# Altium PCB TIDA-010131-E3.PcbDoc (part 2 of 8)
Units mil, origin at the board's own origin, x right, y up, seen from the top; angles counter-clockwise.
Board outline 6889.76 x 5118.11 mil, 6 copper layers (Top Layer, GND Layer, Signal Layer 1, Signal Layer 2, PWR Layer, Bottom Layer), stack 58.5 mil thick; 758 components, 455 nets, 2194 pads, 1156 vias.
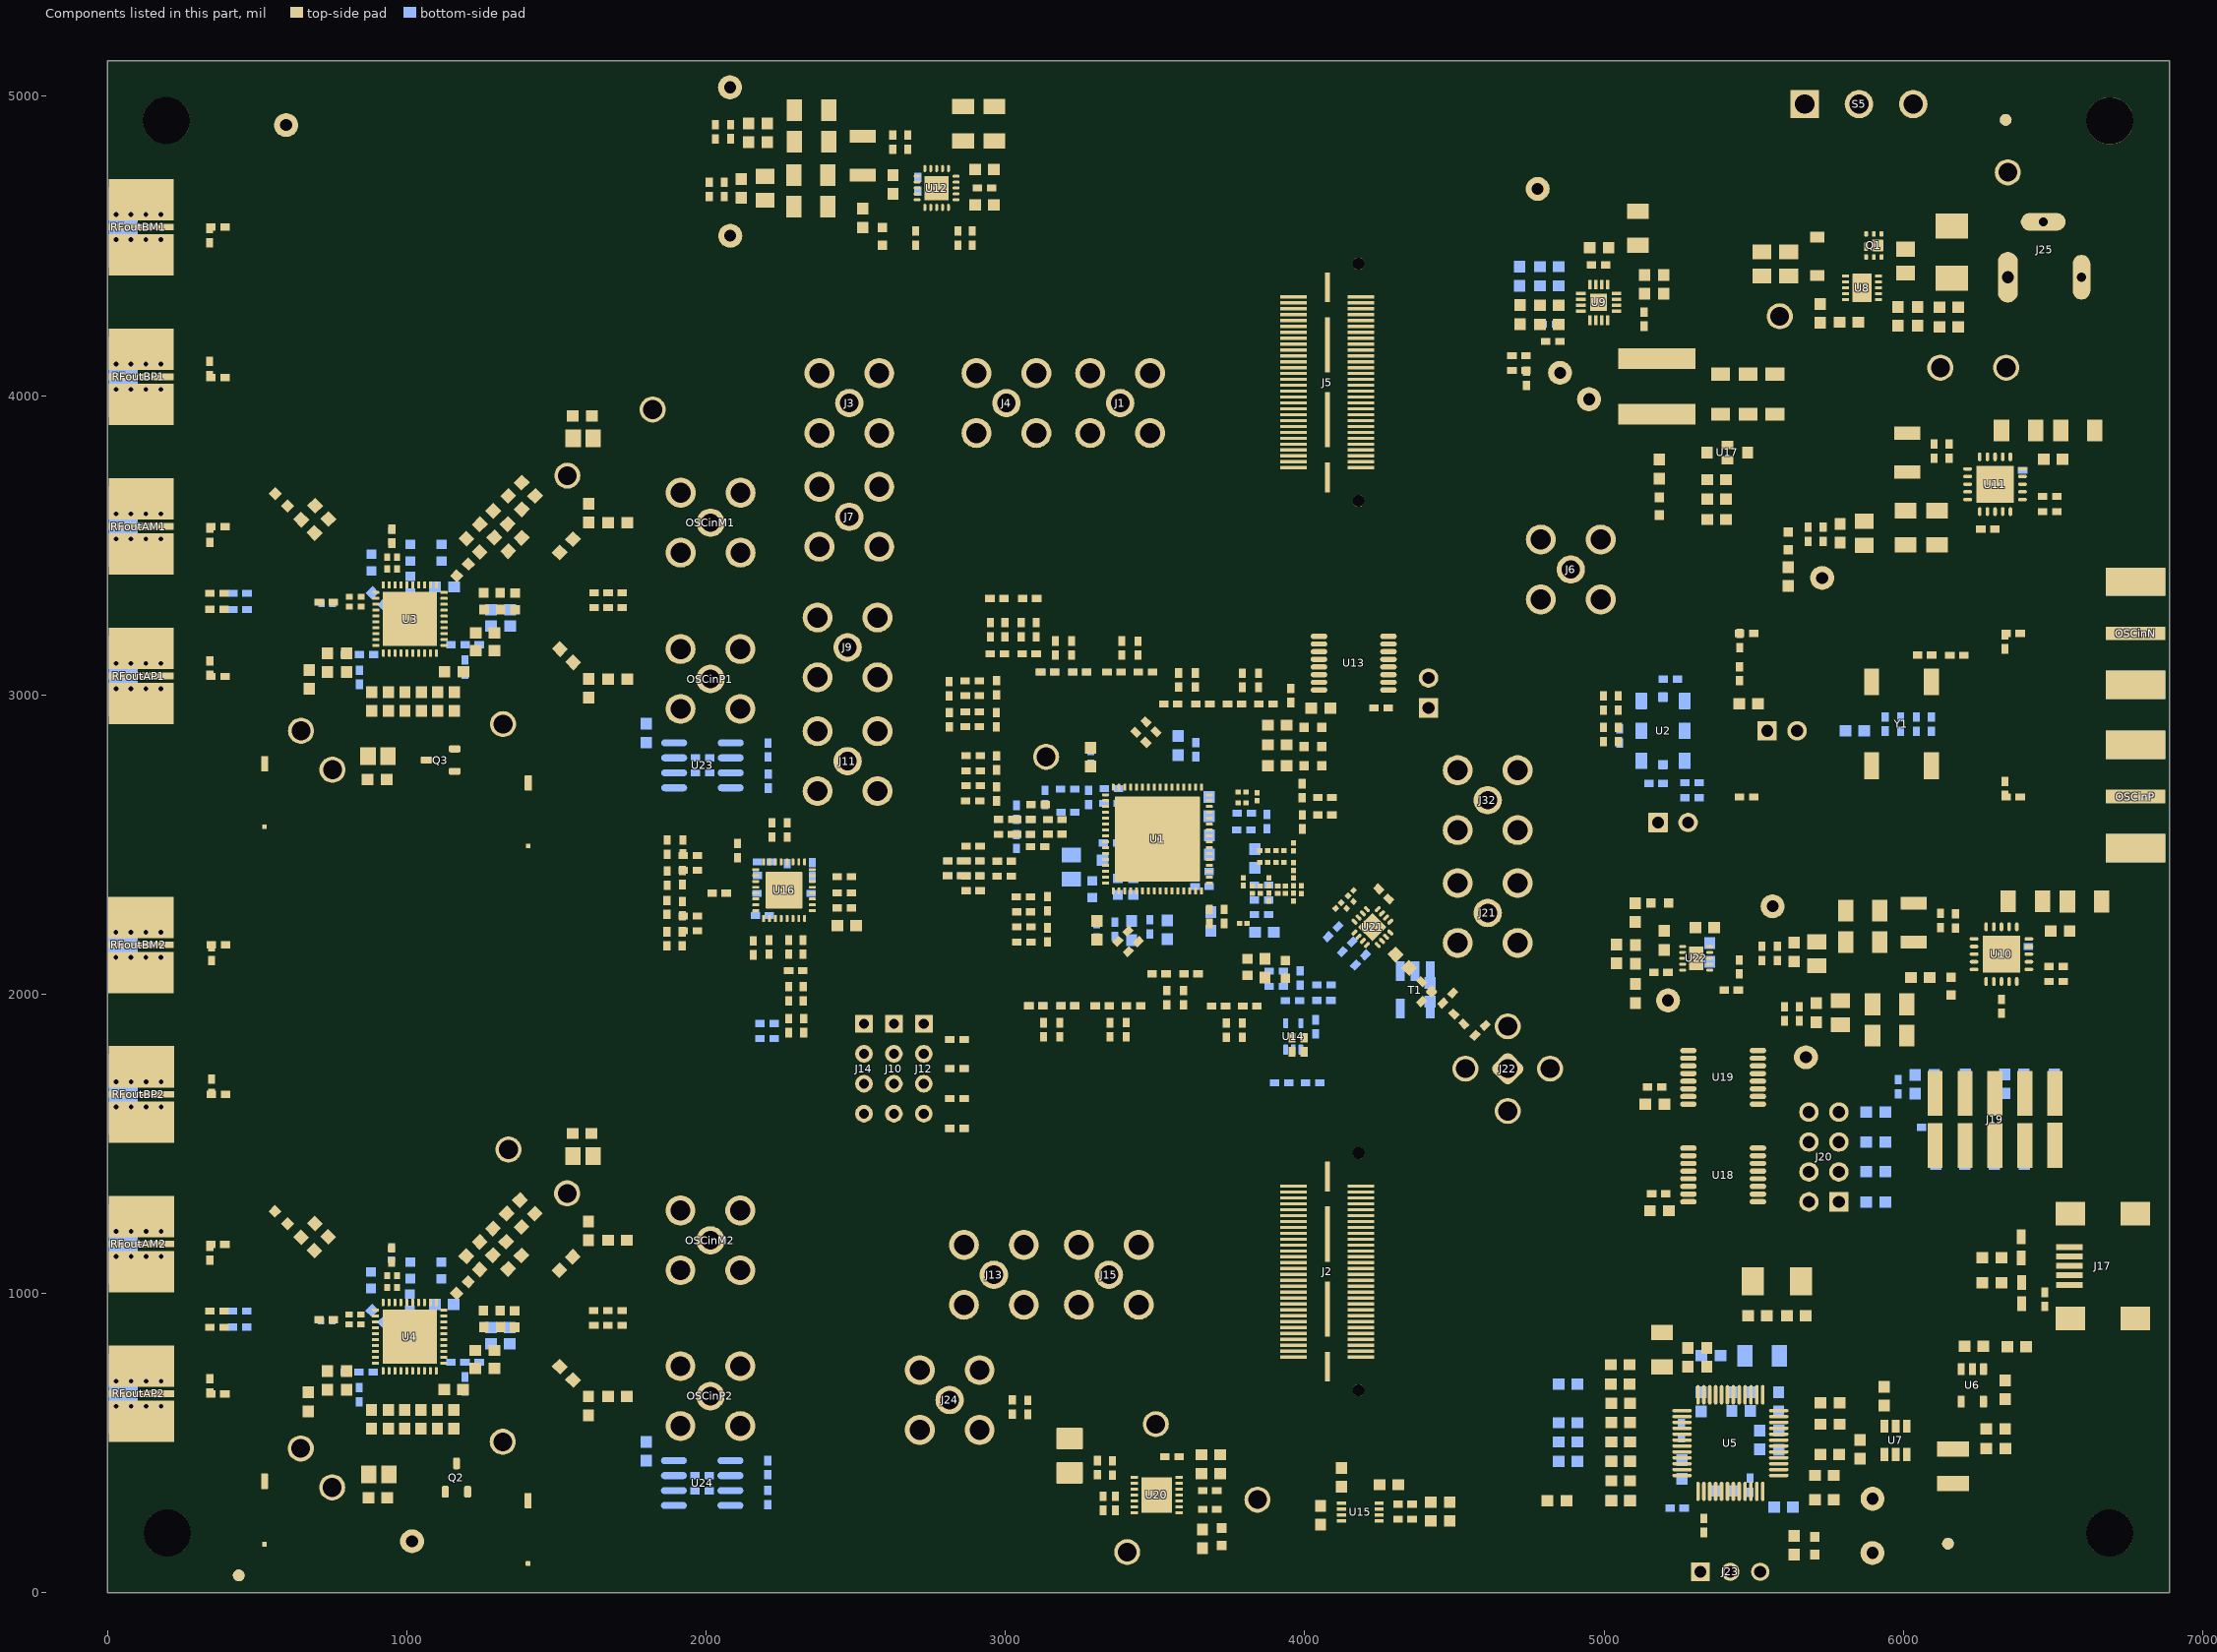
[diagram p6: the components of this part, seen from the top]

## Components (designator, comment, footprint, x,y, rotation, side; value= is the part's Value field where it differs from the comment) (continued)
R100 "CRCW04020000Z0ED" 0402#1 1171.38,3167.62 r180 bottom value=0
R101 "CRCW04020000Z0ED" 0402#1 1988.38,2789.5 r0 bottom value=0
R102 "CRCW0603100RFKEA" 0603 716.21,3609.57 r135 top value=100
R103 "CRCW04020000Z0ED" 0402#1 1649.65,3291.55 r180 top value=0
R104 "CRCW060351R0JNEA" 0603 1607.7,3022.35 r270 top value=51
R105 "RC0603JR-07330RL" 0603 669.92,3563.28 r315 top value=330
R106 "CRCW06030000Z0EA" 0603 1704.7,3053.15 r180 top value=0
R107 "CRCW06030000Z0EA" 0603 1534.1,3130.95 r135 top value=0
R108 "CRCW04020000Z0ED" 0402#1 1696.58,3291.35 r180 top value=0
R109 "CRCW0603100RFKEA" 0603L 1361.7,3312.35 r270 top value=100
R110 "CRCW04020000Z0ED" 0402#1 1696.58,3340.85 r180 top value=0
R111 "CRCW06030000Z0EA" 0603 1704.7,3575.85 r180 top value=0
R112 "CRCW06030000Z0EA" 0603 1533.1,3497.95 r45 top value=0
R113 "CRCW060351R0JNEA" 0603 1607.7,3607.35 r270 top value=51
R114 "CRCW04020000Z0ED" 0402#1 341.97,691.51 r90 top value=0
R115 "FC0402E50R0BST1" 0402L 826.93,897.43 r180 top value=50
R116 "CRCW06030000Z0EA" 0603 1312.95,885.89 r180 bottom value=0
R117 "CRCW04020000Z0ED" 0402#1 341.97,1134.51 r270 top value=0
R118 "CRCW06030000Z0EA" 0603L 1115.85,1077 r270 bottom value=0
R119 "FC0402E50R0BST1" 0402L 826.93,929.8 r180 top value=50
R120 "CRCW06030000Z0EA" 0603L 880.95,1044.44 r270 bottom value=0
R121 "CRCW06030000Z0EA" 0603L 1011.62,1077.14 r270 bottom value=0
R122 "CRCW06030000Z0EA" 0603 670.85,638.07 r270 top value=0
R123 "CRCW0603100KJNEA" 0603 1260.95,749.44 r180 top value=100k
R124 "CRCW06030000Z0EA" 0603 1157.85,579.44 r270 top value=0
R125 "CRCW04020000Z0ED" 0402#1 348.21,2135.47 r270 top value=0
R126 "FC0402E50R0BST1" 0402L 967.08,1039.74 r270 top value=50
R127 "RC0603JR-07270RL" 0603 1360.95,1104.44 r45 top value=270
R128 "CRCW06030000Z0EA" 0603 1309.95,1150.44 r45 top value=0
R129 "CRCW0603120RJNEA" 0603 1355.95,1289.44 r45 top value=120
R130 "FC0402E50R0BST1" 0402L 934.71,1039.74 r90 top value=50
R131 "CRCW04020000Z0ED" 0402#1 348.21,1692.47 r90 top value=0
R132 "CRCW04020000Z0ED" 0402#1 864.47,737.12 r0 bottom value=0
R133 "CRCW0402100RJNED" 0402#1 2207,2815.88 r270 bottom value=100
R134 "CRCW04020000Z0ED" 0402#1 1988,2739.5 r180 bottom value=0
R135 "CRCW0603100RFKEA" 0603 715.45,1211.67 r135 top value=100
R136 "RC0603JR-07330RL" 0603 669.16,1165.38 r315 top value=330
R137 "CRCW04020000Z0ED" 0402#1 1648.89,893.64 r180 top value=0
R138 "CRCW060351R0JNEA" 0603 1606.95,624.44 r270 top value=51
R139 "CRCW06030000Z0EA" 0603 1703.95,656.44 r180 top value=0
R140 "CRCW06030000Z0EA" 0603 1533.35,733.04 r135 top value=0
R141 "CRCW04020000Z0ED" 0402#1 1695.82,893.44 r180 top value=0
R142 "CRCW0603100RFKEA" 0603L 1360.95,914.44 r270 top value=100
R143 "CRCW04020000Z0ED" 0402#1 1695.82,942.94 r180 top value=0
R144 "CRCW06030000Z0EA" 0603 1703.95,1177.94 r180 top value=0
R145 "CRCW06030000Z0EA" 0603 1532.35,1100.04 r45 top value=0
R146 "CRCW060351R0JNEA" 0603 1606.95,1209.44 r270 top value=51
R147 "CRCW060339K0JNEA" 0603 5400.2,340.02 r180 bottom value=39k
R148 "CRCW06030000Z0EA" 0603 6379,822 r180 top value=0
R149 "CRCW060310R0FKEAHP" 0603 6296,1036 r180 top value=10.0
R150 "CRCW060310R0FKEAHP" 0603 6296,1119 r180 top value=10.0
R151 "CRCW060310K0JNEA" 0603 5056.2,504.02 r180 bottom value=10k
R152 "CRCW060310K0JNEA" 0603 5056.2,439.52 r180 bottom value=10k
R153 "CRCW060312K0JNEA" 0603 5427.2,639.02 r270 bottom value=12k
R154 "CRCW0603100RFKEA" 0603 5054.2,697.52 r180 top value=100
R155 "CRCW060310K0JNEA" 0603 5600.2,286.02 r0 bottom value=10k
R156 "CRCW0603100RFKEA" 0603 5056.2,568.52 r180 top value=100
R157 "CRCW0603100RFKEA" 0603 5056.2,504.02 r180 top value=100
R158 "CRCW0603100RFKEA" 0603 5056.2,439.52 r180 top value=100
R159 "CRCW0603100RFKEA" 0603 5056.2,374.02 r180 top value=100
R160 "CRCW060310K0JNEA" 0603 5754.2,462.02 r180 top value=10k
R161 "CRCW060310K0JNEA" 0603 5755.2,634.02 r180 top value=10k
R162 "CRCW060310K0JNEA" 0603 5755.2,563.02 r180 top value=10k
R163 "CRCW06032K00JNEA" 0603 5855.2,479.02 r90 top value=2.0k
R164 "CRCW06031M00FKEA" 0603 6152.18,4295.01 r0 top value=1.00Meg
R165 "CRCW04020000Z0ED" 0402#1 1649.65,3340.55 r0 top value=0
R166 "CRCW060345K3FKEA" 0603 5722.18,4275.01 r90 top value=45.3k
R167 "CRCW060310K0FKEA" 0603 6047.18,4265.01 r90 top value=10.0k
R168 "CRCW04020000Z0ED" 0402#1 1648.61,942.64 r0 top value=0
R169 "CRCW0603100KFKEA" 0603 5818.68,4245.01 r180 top value=100k
R170 "ERJ-2GE0R00X" 0402#1 6327.64,1959.49 r90 top value=0
R171 "ERJ-2GE0R00X" 0402#1 6282.59,3553.87 r0 top value=0
R172 "CRCW04020000Z0ED" 0402#1 5983,1691 r270 bottom value=0
R173 "CRCW04020000Z0ED" 0402#1 6084,1555 r0 bottom value=0
R174 "ERJ-2GE0R00X" 0402#1 6510.19,2042.46 r180 top value=0
R175 "ERJ-2GE0R00X" 0402#1 6488.76,3612.71 r180 top value=0
R176 "ERJ-2GE0R00X" 0402#1 6510.19,2092.46 r180 top value=0
R177 "ERJ-2GE0R00X" 0402#1 6488.76,3662.71 r180 top value=0
R178 "CRCW06030000Z0EA" 0603 5054.2,762.02 r180 top value=0
R179 "ERJ-2GE0R00X" 0402#1 2889.71,4526.5 r90 top value=0
R180 "ERJ-2GE0R00X" 0402#1 2841.71,4526.5 r90 top value=0
R181 "CRCW0603100RFKEA" 0603 5056.2,308.02 r180 top value=100
R182 "CRCW04020000Z0ED" 0402#1 3634.57,3049.4 r90 top value=0
R183 "CRCW04020000Z0ED" 0402#1 3595.2,1987.84 r270 top value=0
R184 "CRCW04020000Z0ED" 0402#1 3539.2,1987.84 r270 top value=0
R185 "CRCW0603100RFKEA" 0603 4880.2,697.02 r180 bottom value=100
R186 "CRCW0603100RFKEA" 0603 4880.2,568.02 r180 bottom value=100
R187 "CRCW0603100RFKEA" 0603 4880.2,504.02 r180 bottom value=100
R188 "CRCW0603100RFKEA" 0603 4880.2,439.52 r180 bottom value=100
R189 "CRCW0603100RFKEA" 0603 4453,302.73 r0 top value=100
R190 "CRCW040247R0JNED" 0402#1 3208.97,2607.66 r180 bottom value=47
R191 "CRCW04020000Z0ED" 0402#1 3998.03,1830.94 r90 top value=0
R192 "CRCW04020000Z0ED" 0402#1 4026.99,1703.56 r180 bottom value=0
R193 "CRCW04020000Z0ED" 0402#1 3959.03,1977.94 r0 bottom value=0
R194 "CRCW04020000Z0ED" 0402#1 3923.4,1703.57 r0 bottom value=0
R195 "CRCW04020000Z0ED" 0402#1 3957.53,1830.94 r270 top value=0
R196 "CRCW04020000Z0ED" 0402#1 4064.65,2030.94 r180 bottom value=0
R197 "CRCW04020000Z0ED" 0402#1 4064.03,1978.94 r180 bottom value=0
R198 "CRCW0402130RFKED" 0402#1 5047.07,2972.6 r270 top value=130
R199 "CRCW0402130RFKED" 0402#1 5048.07,2867.6 r90 top value=130
R200 "CRCW04020000Z0ED" 0402#1 3905.03,2076.94 r0 bottom value=0
R201 "CRCW04020000Z0ED" 0402#1 3985.03,2053.94 r90 bottom value=0
R202 "CRCW04020000Z0ED" 0402#1 3905.03,2025.94 r0 bottom value=0
R203 "ERJ-1GN0R00C" 0201 3917.97,2479.66 r180 top value=0
R204 "RC0201JR-0751RL" 0201 3962.97,2492.65 r270 top value=51
R205 "CRCW060310K0JNEA" 0603 5056.2,308.02 r180 bottom value=10k
R206 "CRCW0603100RFKEA" 0603 4843,308 r180 top value=100
R207 "CRCW0603100RFKEA" 0603 4123,386 r90 top value=100
R208 "CRCW04020000Z0ED" 0402#1 3953.64,2998.06 r90 top value=0
R209 "CRCW040212K0JNED" 0402#1 4254.72,2956.39 r180 top value=12k
R210 "CRCW060333R0JNEA" 0603 6104,1699.5 r90 bottom value=33
R211 "CRCW06030000Z0EA" 0603 6039,1699 r90 bottom value=0
R212 "CRCW06030000Z0EA" 0603 5055.2,633.02 r180 top value=0
R213 "CRCW040210K0DHEDP" 0402#1 1195,3093 r270 bottom value=10.0k
R214 "CRCW040210K0DHEDP" 0402#1 842,3059 r270 bottom value=10.0k
R215 "CRCW040210K0DHEDP" 0402#1 1195,697.38 r270 bottom value=10.0k
R216 "CRCW040210K0DHEDP" 0402#1 841,662 r270 bottom value=10.0k
R217 "CRCW06031K00FKEA" 0603 5635.2,159.02 r90 top value=1.00k
R218 "CRCW04020000Z0ED" 0402#1 4335,295.73 r0 top value=0
R219 "CRCW04020000Z0ED" 0402#1 4335,245.73 r0 top value=0
R220 "CRCW06031K00FKEA" 0603 5184.3,3754.34 r90 top value=1.00k
R221 "CRCW060333K2FKEA" 0603 5199.97,4371.66 r90 top value=33.2k
R222 "CRCW06031K00FKEA" 0603 5615.85,3394.98 r270 top value=1.00k
R223 "CRCW06031K00FKEA" 0603 6056.86,2055.48 r180 top value=1.00k
R224 "CRCW06031K00FKEA" 0603 2523,4593 r90 top value=1.00k
R225 "CRCW0603100RFKEA" 0603 4453,239.73 r0 top value=100
R226 "CRCW060348K7FKEA" 0603 5135.97,4371.66 r270 top value=48.7k
R227 "ERJ-1GN0R00C" 0201 3923,2336.99 r180 top value=0
R228 "CRCW060351R1FKEA" 0603 4717.97,4398.66 r90 bottom value=51.1
R229 "RG1608P-104-B-T5" 0603 4816.97,4366.66 r180 bottom value=100k
R230 "CRCW060331K6FKEA" 0603 4816.97,4430.66 r0 bottom value=31.6k
R231 "CRCW06034K99FKEA" 0603 4816.97,4301.66 r0 top value=4.99k
R232 "CRCW0603182KFKEA" 0603 4816.97,4237.66 r0 top value=182k
R233 "CRCW04020000Z0ED" 0402#1 2104.82,2479.41 r90 top value=0
R234 "CRCW04020000Z0ED" 0402#1 2043.82,2337.41 r180 top value=0
R235 "CRCW04020000Z0ED" 0402#1 2461.82,2337.91 r0 top value=0
R236 "CRCW04020000Z0ED" 0402#1 2461.82,2392.91 r0 top value=0
R237 "CRCW04020000Z0ED" 0402#1 2219.82,2548.41 r90 top value=0
R238 "CRCW04020000Z0ED" 0402#1 2270.82,2548.91 r90 top value=0
R239 "CRCW04020000Z0ED" 0402#1 2210.82,2156.91 r270 top value=0
R240 "CRCW04020000Z0ED" 0402#1 1947.32,2463.2 r180 top value=0
R241 "CRCW04020000Z0ED" 0402#1 1947.32,2414.2 r180 top value=0
R242 "CRCW04020000Z0ED" 0402#1 1947.32,2260.91 r180 top value=0
R243 "CRCW04020000Z0ED" 0402#1 1947.32,2211.91 r180 top value=0
R244 "CRCW04020000Z0ED" 0402#1 2275.82,2000.91 r90 top value=0
R245 "CRCW0402160RJNED" 0402#1 1869.32,2184.91 r90 top value=160
R246 "CRCW0402160RJNED" 0402#1 1869.32,2289.91 r270 top value=160
R247 "CRCW0402160RJNED" 0402#1 1869.82,2387.41 r90 top value=160
R248 "CRCW0402160RJNED" 0402#1 1869.82,2491.41 r270 top value=160
R249 "CRCW0402100RFKED" 0402#1 2299.82,2078.91 r180 top value=100
R250 "CRCW04020000Z0ED" 0402#1 2324.82,2000.91 r90 top value=0
R251 "CRCW04020000Z0ED" 0402#1 2838.47,1848.66 r0 bottom value=0
R252 "CRCW04020000Z0ED" 0402#1 2838.47,1848.66 r0 top value=0
R253 "CRCW04020000Z0ED" 0402#1 2838.47,1751.66 r0 bottom value=0
R254 "CRCW04020000Z0ED" 0402#1 2838.47,1751.66 r0 top value=0
R255 "CRCW04020000Z0ED" 0402#1 2838.1,1651.66 r0 bottom value=0
R256 "CRCW04020000Z0ED" 0402#1 2838.1,1651.66 r0 top value=0
R257 "CRCW04020000Z0ED" 0402#1 2838.1,1551.66 r0 bottom value=0
R258 "CRCW04020000Z0ED" 0402#1 2838.1,1551.66 r0 top value=0
R259 "CRCW04020000Z0ED" 0402#1 4716,4133 r180 top value=0
R260 "CRCW04020000Z0ED" 0402#1 4741,4058 r90 top value=0
R261 "CRCW04020000Z0ED" 0402#1 4716,4084 r180 top value=0
R262 "CRCW04020000Z0ED" 0402#1 1922.32,2491.91 r90 top value=0
R263 "CRCW04020000Z0ED" 0402#1 2203.94,1901.91 r0 bottom value=0
R264 "CRCW04020000Z0ED" 0402#1 1921.32,2389.91 r270 top value=0
R265 "CRCW04020000Z0ED" 0402#1 2203.94,1851.91 r0 bottom value=0
R266 "CRCW04020000Z0ED" 0402#1 1921.32,2285.91 r90 top value=0
R267 "CRCW04020000Z0ED" 0402#1 2276.07,1895.16 r90 top value=0
R268 "CRCW04020000Z0ED" 0402#1 1920.32,2184.91 r270 top value=0
R269 "CRCW04020000Z0ED" 0402#1 2326.07,1895.16 r90 top value=0
R270 "RC0603FR-0782RL" 0603 5482.97,2970.66 r180 top value=82.0
R271 "ERJ-1GN0R00C" 0201 3923,2361.99 r180 top value=0
R272 "CRCW020149R9FKED" 0201 3963,2375 r270 top value=49.9
R273 "CRCW020149R9FKED" 0201 3881,2374.99 r270 top value=49.9
R274 "CRCW04020000Z0ED" 0402#1 442.66,3285.4 r180 bottom value=0
R275 "CRCW04020000Z0ED" 0402#1 442.66,3338.9 r180 bottom value=0
R276 "CRCW0402100RJNED" 0402#1 2208,2712.12 r270 bottom value=100
R277 "CRCW04020000Z0ED" 0402#1 1170.62,769.72 r180 bottom value=0
R278 "CRCW04020000Z0ED" 0402#1 441.9,887.5 r180 bottom value=0
R279 "CRCW04020000Z0ED" 0402#1 441.9,941 r180 bottom value=0
R280 "CRCW04020000Z0ED" 0402#1 1987,391.5 r0 bottom value=0
R281 "CRCW0402100RJNED" 0402#1 2206,417.88 r270 bottom value=100
R282 "CRCW040220R0FKED" 0402#1 3452.55,2858.06 r135 top value=20.0
R283 "CRCW040220R0FKED" 0402#1 3486.49,2893.42 r135 top value=20.0
R284 "CRCW04020000Z0ED" 0402#1 2892.97,2796.66 r180 top value=0
R285 "CRCW04020000Z0ED" 0402#1 2890.97,2645.66 r0 top value=0
R286 "CRCW0402120RJNED" 0402#1 3165.97,2583.66 r180 top value=120
R287 "CRCW0402120RJNED" 0402#1 3165.97,2534.66 r180 top value=120
R288 "CRCW0402120RJNED" 0402#1 2996.6,2444.66 r180 top value=120
R289 "CRCW0402120RJNED" 0402#1 2995.97,2394.66 r180 top value=120
R290 "CRCW04020000Z0ED" 0402#1 3059.97,2325.66 r180 top value=0
R291 "CRCW04020000Z0ED" 0402#1 3061.97,2173.66 r180 top value=0
R292 "CRCW040220R0FKED" 0402#1 3392.69,2193.7 r45 top value=20.0
R293 "CRCW040220R0FKED" 0402#1 3427.34,2159.05 r45 top value=20.0
R294 "ERJ-3EKF4752V" 0603 2624.79,4705.15 r90 top value=47.5k
R295 "ERJ-2GE0R00X" 0402#1 2699.71,4526.5 r90 top value=0
R296 "CRCW060333R0JNEA" 0603 6108,1464 r270 bottom value=33
R297 "CRCW04020000Z0ED" 0402#1 3132.84,2657.28 r90 bottom value=0
R298 "CRCW04020000Z0ED" 0402#1 2891.97,2344.66 r0 bottom value=0
R299 "CRCW04020000Z0ED" 0402#1 6178.97,3132.66 r0 top value=0
R300 "CRCW04020000Z0ED" 0402#1 1987,340.5 r180 bottom value=0
R301 "CRCW0402100RJNED" 0402#1 2206,317.88 r270 bottom value=100
R302 "CRCW060333R0JNEA" 0603 6205,1464 r90 bottom value=33
R303 "CRCW060333R0JNEA" 0603 6404,1464 r90 bottom value=33
R304 "CRCW06030000Z0EA" 0603 6304,1464 r90 bottom value=0
R305 "CRCW060333R0JNEA" 0603 6403,1700 r270 bottom value=33
R306 "CRCW060333R0JNEA" 0603 6505,1700 r270 bottom value=33
R307 "CRCW060333R0JNEA" 0603 6207,1700 r270 bottom value=33
R308 "CRCW060310K0JNEA" 0603 5908,1305 r180 bottom value=10k
R309 "CRCW060310K0JNEA" 0603 5908,1407 r180 bottom value=10k
R310 "CRCW060310K0JNEA" 0603 5908,1506 r180 bottom value=10k
R311 "CRCW060333R0JNEA" 0603 6339,1700 r270 bottom value=33
R312 "CRCW060310K0JNEA" 0603 5908,1606 r180 bottom value=10k
R313 "CRCW04020000Z0ED" 0402#1 5183,1333 r0 top value=0
R314 "CRCW04020000Z0ED" 0402#1 5169,1689.93 r0 top value=0
R315 "CRCW06030000Z0EA" 0603 4053,259 r90 top value=0
R316 "ERJ-2RKF1002X" 0402#1 3682.51,278.24 r0 top value=10.0k
R317 "ERJ-2RKF1002X" 0402#1 3682.51,341.24 r0 top value=10.0k
R318 "ERJ-2RKF1002X" 0402#1 3556.51,454.24 r180 top value=10.0k
R319 "CRCW0603750RJNEA" 0603 3658.51,180.24 r270 top value=750
R320 "RC0603JR-071K3L" 0603 3686.51,398.24 r0 top value=1.3k
R321 "RC0603JR-071K3L" 0603 3686.51,461.24 r0 top value=1.3k
R322 "CRCW04020000Z0ED" 0402#1 4407.34,2025.01 r315 top value=0
R323 "CRCW040233K0JNED" 0402#1 3023,620.38 r270 top value=33k
R324 "CRCW0402100KFKED" 0402#1 3075,619.62 r270 top value=100k
R325 "CRCW04020000Z0ED" 0402#1 5452,2091 r270 top value=0
R326 "CRCW0402100KFKED" 0402#1 5190,2073 r0 top value=100k
R327 "ERJ-1GN0R00C" 0201 4131,2296 r315 top value=0
R328 "ERJ-1GN0R00C" 0201 4154,2319 r315 top value=0
R329 "CRCW04020000Z0ED" 0402#1 5425,2014 r180 top value=0
R330 "CRCW04020000Z0ED" 0402#1 4407.34,1991.6 r225 top value=0
R331 "CRCW060325K5FKEA" 0603 5042,2134 r90 top value=25.5k
R332 "CRCW060311K8FKEA" 0603 5105,2002 r90 top value=11.8k
R333 "ERJ-1GN0R00C" 0201 4112.63,2296 r45 top value=0
R334 "ERJ-1GN0R00C" 0201 4154,2337.37 r225 top value=0
R335 "CRCW04020000Z0ED" 0402#1 5333.63,225 r90 top value=0
R336 "CRCW04020000Z0ED" 0402#1 2950,3217.62 r90 top value=0
R337 "CRCW04020000Z0ED" 0402#1 3103,3217.62 r270 top value=0
R338 "CRCW04020000Z0ED" 0402#1 2889.84,2894.18 r180 top value=0
R339 "CRCW04020000Z0ED" 0402#1 2889.38,3047 r0 top value=0
R340 "CRCW04020000Z0ED" 0402#1 5259,542.38 r270 bottom value=0
R341 "CRCW04020000Z0ED" 0402#1 5244,282.63 r0 bottom value=0
R342 "CRCW06031K00FKEA" 0603 5104,2273 r270 top value=1.00k
R343 "ERJ-2RKF1002X" 0402#1 3278,2657.69 r270 bottom value=10.0k
R344 "ERJ-2RKF1000X" 0402#1 3060.78,2533.78 r180 bottom value=100
R345 "ERJ-2RKF1000X" 0402#1 3061.16,2583.78 r180 bottom value=100
R346 "ERJ-2RKF1000X" 0402#1 2891.57,2445.18 r0 bottom value=100
R347 "ERJ-2RKF1000X" 0402#1 2891.57,2396.18 r0 bottom value=100
R348 "CRCW04020000Z0ED" 0402#1 1218.62,3167.62 r0 bottom value=0
R349 "CRCW04020000Z0ED" 0402#1 818.38,3134.62 r180 bottom value=0
R350 "CRCW04020000Z0ED" 0402#1 3000.38,2534 r180 top value=0
R351 "CRCW04020000Z0ED" 0402#1 3000.76,2584 r180 top value=0
R352 "CRCW04020000Z0ED" 0402#1 1218.62,769.72 r0 bottom value=0
R353 "CRCW04020000Z0ED" 0402#1 817.22,737.12 r180 bottom value=0
R354 "CRCW04020000Z0ED" 0402#1 2830.79,2395.4 r180 top value=0
R355 "CRCW04020000Z0ED" 0402#1 2831.17,2445.4 r180 top value=0
R356 "ERJ-2RKF1000X" 0402#1 3081,3322 r180 top value=100
R357 "ERJ-2RKF1000X" 0402#1 2972,3322 r0 top value=100
R358 "CRCW04020000Z0ED" 0402#1 3037.16,2510.16 r90 bottom value=0
R359 "CRCW04020000Z0ED" 0402#1 3037.54,2607.4 r270 bottom value=0
R360 "CRCW04020000Z0ED" 0402#1 2830.79,2395.4 r0 bottom value=0
R361 "CRCW04020000Z0ED" 0402#1 2831.17,2445.4 r0 bottom value=0
R362 "CRCW04020000Z0ED" 0402#1 366.38,3286 r0 top value=0
R363 "CRCW04020000Z0ED" 0402#1 366.38,3339 r0 top value=0
R364 "CRCW04020000Z0ED" 0402#1 366.38,886.89 r0 top value=0
R365 "CRCW04020000Z0ED" 0402#1 366.38,940.66 r0 top value=0
R366 "ERJ-2RKF1000X" 0402#1 2812.31,3020.55 r270 top value=100
R367 "ERJ-2RKF1000X" 0402#1 2813,2917 r90 top value=100
RFoutAM1 "142-0771-831" JOHNSON_142-0771-831 3.65,3562.93 r90 top
RFoutAM2 "142-0771-831" JOHNSON_142-0771-831 4.38,1165.1 r90 top
RFoutAP1 "142-0771-831" JOHNSON_142-0771-831 3.65,3063 r90 top
RFoutAP2 "142-0771-831" JOHNSON_142-0771-831 4.38,665.1 r90 top
RFoutBM1 "142-0771-831" JOHNSON_142-0771-831 3.65,4562.93 r90 top
RFoutBM2 "142-0771-831" JOHNSON_142-0771-831 3.39,2164.53 r90 top
RFoutBP1 "142-0771-831" JOHNSON_142-0771-831 3.65,4062.93 r90 top
RFoutBP2 "142-0771-831" JOHNSON_142-0771-831 4.38,1665.1 r90 top
RMPCLK1 "5007" Keystone5007 646.8,2880 r90 top value=White
RMPCLK2 "5007" Keystone5007 646.04,482.1 r90 top value=White
RMPDIR1 "5007" Keystone5007 751.8,2750 r90 top value=White
RMPDIR2 "5007" Keystone5007 751.04,352.1 r90 top value=White
S1 "TCBS-6-01" TCBS-6-01 200,200 r180 bottom
S2 "TCBS-6-01" TCBS-6-01 197,4919 r180 bottom
S3 "TCBS-6-01" TCBS-6-01 6689.76,4918.11 r180 bottom
S4 "TCBS-6-01" TCBS-6-01 6689.76,200 r180 bottom
S5 "L101011MS02Q" "SW_ L101011MS02Q" 5852,4861.5 r90 top locked
SYNC "5007" Keystone5007 3136,2793 r0 top value=White
T1 "TC1-1-13M+" TFMR_5_150X150_50 4369,2014.5 r270 bottom
TP1 "5000" Keystone5000 597,4904 r0 top
TP2 "5000" Keystone5000 1018,172 r0 top
TP4 "5010" Keystone5010 6343.66,4093.3 r180 top
TP5 "5010" Keystone5010 5587.18,4265.01 r180 top
TP6 "5012" Keystone5012 6123.66,4093.3 r180 top
TP7 "5011" Keystone5011 6349,4746 r270 top
TP8 "5000" Keystone5000 5674.43,1789.25 r180 top
TP9 "5000" Keystone5000 5728.73,3390.8 r90 top
TP10 "5000" Keystone5000 5563.12,2293.49 r90 top
TP11 "5000" Keystone5000 2081,4534 r90 top
TP12 "5000" Keystone5000 2080.13,5029.92 r0 top
TP13 "5000" Keystone5000 4950,3988 r0 top
TP14 "5000" Keystone5000 4778.38,4690.56 r0 top
TP15 "5000" Keystone5000 4853,4076 r0 top
TP16 "5000" Keystone5000 5897,133 r90 top
TP17 "5007" Keystone5007 3407,136 r0 top value=White
TP18 "5007" Keystone5007 3502.51,563.24 r0 top value=White
TP19 "5007" Keystone5007 3842.31,311.1 r0 top value=White
TP20 "5000" Keystone5000 5214,1979 r90 top
U1 "LMK04828" NKD0064A 3507.83,2518.62 r0 top locked
U2 "LMK61E2-SIAT" SIA0008B 5197.07,2879.81 r0 bottom
U3 "LMX2594RHAT" RHA0040A 1010.7,3253.55 r180 top
U4 "LMX2594RHAT" RHA0040A 1009.95,855.64 r180 top locked
U5 "FT232HL-REEL" LQFP-48_N 5422.2,500.02 r270 top
U6 "TLV70233DBVT" DBV0005A_N 6230.5,693 r270 top
U7 "93LC56BT-I/OT" SOT-23-6 5974.2,509.02 r90 top
U8 "TPS259250DRCT" DRC0010J 5862.18,4360.01 r180 top
U9 "TPS54318RTE" RTE-16 4981.97,4311.66 r270 top
U10 "TPS7A4700RGWR" RGW0020A 6327.9,2133.66 r0 top
U11 "TPS7A4700RGWR" RGW0020A 6306.46,3703.91 r0 top
U12 "TPS7A8300RGRR" RGR0020A 2770.46,4693.67 r0 top
U13 "TMUX1574PWR" PW0016A_N 4163.86,3105.98 r180 top
U14 "SN74LVC1G08DCKR" DCK0005A_N 3961.97,1858.94 r90 bottom
U15 "SN74LVC2G53DCU" VSSOP8 4186,269.73 r0 top
U16 "LMK00304SQ/NOPB" RTV0032A 2260.61,2347.39 r0 top
U17 "NFM31PC276B0J3L" Murata_NFM31P 5412,3810 r180 top value="27 uF"
U18 "TMUX1574PWR" PW0016A_N 5398.14,1395.98 r180 top
U19 "TMUX1574PWR" PW0016A_N 5398,1722 r180 top
U20 "LM95233CISD" SDA14B 3505.57,326.8 r0 top
U21 "NB7V33MMNTXG" QFN16-3x3MM_0_5 4226,2224 r135 top
U22 "TPS7A9001DSKR" DSK0010A 5307.99,2119.8 r0 top
U23 "DS90LV028AQMA" M08A_N 1988,2764.5 r180 bottom
U24 "DS90LV028AQMA" M08A_N 1987,366.5 r180 bottom
Vcc_TP1 "5007" Keystone5007 1821.65,3953.55 r180 top value=White
Vcc_TP2 "5007" Keystone5007 1340,1481 r180 top value=White
VCCCORE "5000" Keystone5000 5897.2,314.02 r180 top
Vtune_TP1 "5007" Keystone5007 1536.7,3732.35 r180 top value=White
Vtune_TP2 "5007" Keystone5007 1535.95,1334.44 r180 top value=White
Y1 "CVHD-950-100.000" OSC_CVHD-950-4 5993.97,2903.39 r270 top
Y2 "ABM3-12.000MHZ-B2-T" XTAL_ABM3 5577.51,1040.93 r180 top
ZZ1 "This Assembly Note is for PCB labels only" AssemblyNoteLabel -305,2336.55 r0 top
ZZ2 "These assemblies are ESD sensitive, ESD precautions shall be observed." AssemblyNote -309,2282.55 r0 top
ZZ3 "These assemblies must be clean and free from flux and all contaminants. Use of no clean flux is not acceptable." AssemblyNote -305,2212.55 r0 top
ZZ4 "These assemblies must comply with workmanship standards IPC-A-610 Class 2, unless otherwise specified." AssemblyNote -297,2142.55 r0 top

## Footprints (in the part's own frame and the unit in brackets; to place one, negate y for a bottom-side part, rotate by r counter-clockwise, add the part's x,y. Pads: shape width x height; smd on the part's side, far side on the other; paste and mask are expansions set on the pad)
0201 [mm] "Data from Kemet datasheet CC101_COM dated 7/28/11"
  rect 0.46x0.42 smd mask+0.048: 1(-0.33,0) 2(0.33,0)
  silkscreen extent -0.25,-0.38 0.13,0.38, body extent -0.31,-0.16 0.31,0.16, height 0.26
0201_033 [mm] "SMD, 2-Leads, Height 0.33mm"
  rect 0.46x0.42 smd mask+0.048: 1(-0.33,0) 2(0.33,0)
  body extent -0.31,-0.16 0.31,0.16, height 0.33
0402#1 [mm] "0402 from SM-752 data"
  rect 0.8x0.6 smd: 1(-0.6,0) 2(0.6,0)
  silkscreen extent -1.22,-0.52 1.22,0.52, body extent -0.55,-0.3 0.55,0.3, height 0.6
0402#2 [mm] "0402 from SM-752 data"
  rect 0.6x0.8 smd: 1(173.565,-27.125) 2(173.565,-28.325)
  silkscreen extent 173.04,-28.94 174.09,-26.51, body extent 173.27,-28.27 173.86,-27.18, height 0.6
0402_065 [mm] "0402"
  rect 0.8x0.6 smd: 1(-0.6,0) 2(0.6,0)
  body extent -0.55,-0.3 0.55,0.3, height 0.65
0402L [mm] "0402 from SM-752 data"
  rect 0.6x0.5 smd: 1(-0.5,0) 2(0.5,0)
  body extent -0.55,-0.3 0.55,0.3, height 0.6
0603 [mm] "0603 from SM-752 data"
  rect 1x0.95 smd: 1(-0.8,0) 2(0.8,0)
  silkscreen extent -1.52,-0.69 1.52,0.69, body extent -0.87,-0.47 0.87,0.47, height 1
0603L [mm] "0603 from SM-752 data"
  rect 0.8x0.85 smd: 1(-0.7,0) 2(0.7,0)
  silkscreen extent -0.07,-0.32 0.07,0.32, body extent -0.87,-0.47 0.87,0.47, height 1
0805 [mm] "0805 from SM-752 data"
  rect 1.3x1.5 smd: 1(-0.85,0) 2(0.85,0)
  silkscreen extent -1.72,-0.97 1.72,0.97, body extent -1.1,-0.72 1.1,0.72, height 1.45
0805_HV [mil] "0805 with 30mil clearance between pads"
  rect 50x63 smd: 1(-40,0) 2(40,0)
  silkscreen extent -74,-40 74,40, body extent -43,-29 43,29, height 57
1206 [mm] "1206 from SM-752 data"
  rect 1.3x1.85 smd: 1(-1.45,0) 2(1.45,0)
  silkscreen extent -2.4,-1.21 2.4,1.21, body extent -1.7,-0.9 1.7,0.9, height 1.35
1206_190 [mm] "1206_190"
  rect 1.1x1.6 smd: 1(-1.7,0) 2(1.7,0)
  silkscreen extent -0.9,-1 0.9,1, body extent -1.75,-0.95 1.75,0.95, height 1.9
1210_270 [mm] "1210"
  rect 1.3x2.7 smd: 1(-1.45,0) 2(1.45,0)
  silkscreen extent -2.32,-1.57 2.32,1.57, body extent -1.7,-1.35 1.7,1.35, height 2.7
1210_280 [mm] "SMD, 2-Leads, Body 3.6x2.8mm, Height 2.8mm"
  rect 1.1x2.2 smd: 1(-1.65,0) 2(1.65,0)
  silkscreen extent -0.84,-1.4 0.84,1.4, body extent -1.8,-1.4 1.8,1.4, height 2.8
3528-21 [mm] "Medium Density IPC, based on Kemet datasheet 2016-10-20"
  rrect6% 1.8x2.23 smd: 1(-1.46,0) 2(1.46,0)
  silkscreen extent -2.29,-1.5 0.76,1.5, body extent -1.85,-1.5 1.85,1.5, height 2.12
651305142821 [mm] "5 pins"
  rect 0.5x2.25 smd: 1(-1.6,2.8) 2(-0.8,2.8) 3(0,2.8) 4(0.8,2.8) 5(1.6,2.8)
  rect 2x2.5 smd: Shell(-4.45,-2.8) Shell(-4.45,2.7) Shell(4.45,2.7) Shell(4.45,-2.8)
  silkscreen extent -3.85,-5.74 3.85,4.1, body extent -4.95,-5.74 4.95,3.66
AssemblyNote [mil] "Assembly Note"
AssemblyNoteLabel [mil] "Assembly Note for PCB Labels"
CONN_RAPC722X [mm] "Conn_DC Jack"
  oval 1.7x4.3 hole 1.01 slot 3.56 at 90 deg: 1(-13.741,0)
  oval 1.5x3.8 hole 0.76 slot 3.05 at 90 deg: 2(-7.493,0)
  oval 3.8x1.5 hole 0.76 slot 3.05 at 0 deg: 3(-10.744,4.7)
  silkscreen extent -14.48,-4.57 0.25,4.57, body extent -14.5,-4.57 0.23,4.83, height 11.18
DBV0005A_N [mm] "SOT23, 5-Leads, Body 2.9x1.6mm, Pitch 0.95mm, Lead Span 2.8mm, IPC Medium Density"
  rrect17% 1x0.6 smd: 1(-1.375,0.95) 2(-1.375,0) 3(-1.375,-0.95) 4(1.375,-0.95) 5(1.375,0.95)
  silkscreen extent -1.63,-1.55 0.38,1.55, body extent -1.42,-1.46 1.42,1.46, height 1.09
DCK0005A_N [mm] "SOT353, 5-Leads, Body 2x1.3mm, Pitch 0.65mm, Lead Span 2.1mm, IPC Medium Density"
  rrect25% 0.85x0.4 smd: 1(-1.125,0.65) 2(-1.125,0) 3(-1.125,-0.65) 4(1.125,-0.65) 5(1.125,0.65)
  silkscreen extent -1.48,-1.02 0.55,1.1, body extent -1.14,-1 1.14,1, height 0.95
DQK0006C [mm] "WSON"
  rrect12% 0.9x0.86 on Top Paste: 0(0,0.325)
  rrect34% 0.7x0.29 on Top Paste: 0(0.095,-0.65)
  rrect33% 0.45x0.3 smd: 1(-0.975,0.65) 2(-0.975,0) 3(-0.975,-0.65) 4(0.975,-0.65) 5(0.975,0) 6(0.975,0.65)
  rrect33% 0.75x0.3 smd paste-0.15: 7(0.095,-0.65)
  rrect11% 1x0.95 smd paste-0.5: 8(0,0.325)
  silkscreen extent -1.15,-1.15 1.15,1.15, body extent -1,-1 1,1, height 0.82
DRC0010J [mm] "SON, 10-Leads, Body 3x3mm, Pitch 0.5mm, Thermal Pad 2.4x1.65mm, TI Recommended"
  rrect42% 0.6x0.24 smd: 1(-1.4,1) 2(-1.4,0.5) 3(-1.4,0) 4(-1.4,-0.5) 5(-1.4,-1) 6(1.4,-1) 7(1.4,-0.5) 8(1.4,0) 9(1.4,0.5) 10(1.4,1)
  rrect6% 1.65x2.4 smd paste-0.825: 11(0,0)
  silkscreen extent -1.7,-1.7 1.7,1.7, body extent -1.5,-1.5 1.5,1.5, height 0.77
DSK0010A [mm] "SON, 10-Leads, Body 2.5x2.5mm, Pitch 0.5mm, Thermal Pad 2x1.2mm - ADI"
  oval 0.6x0.25 smd: 1(-1.15,1) 2(-1.15,0.5) 3(-1.15,0) 4(-1.15,-0.5) 5(-1.15,-1) 6(1.15,-1) 7(1.15,-0.5) 8(1.15,0) 9(1.15,0.5) 10(1.15,1)
  rect 1.2x2 smd paste-0.6: 11(0,0)
  silkscreen extent -1.3,-1.45 1.3,1.45, body extent -1.25,-1.25 1.25,1.25, height 0.8
EMERSON_142-0701-851 [mil] "Johnson Components"
  rect 45x200 smd: 1(0,-110)
  rect 95x200 smd: 2(-172.5,-110) 3(172.5,-110)
  rect 95x200 smd far side: 4(172.5,-110) 5(-172.5,-110)
  silkscreen extent -235,-220 235,0, body extent -190,-195 190,387, height 155
ESD_Overlay_SMALL [mil]
  silkscreen extent -62,-48 64,61
FCC_disclaimer [mil]
FCI_52601-S10-8LF [mil] "FCI Electronics"
  rect 150x50 smd: 1(-87.5,200) 2(86.5,200) 3(-87.5,100) 4(87.5,100) 5(-87.5,0) 6(87.5,0) 7(-87.5,-100) 8(87.5,-100) 9(-87.5,-200) 10(87.5,-200)
  silkscreen extent -175,-396 176,397, body extent -172,-395 173,395, height 496
Fiducial10-20 [mm]
  round 1 smd mask+0.5: 1(0,0)
  Top Layer keep-out circle w1.178: c0,0 r0.5
IND_LQG15H [mm] "MuRata"
  rect 0.55x0.6 smd: 1(-0.475,0) 2(0.475,0)
  silkscreen extent -1.3,-0.3 -0.95,0.3, body extent -0.52,-0.27 0.52,0.27, height 0.55
JOHNSON_142-0701-20X [mil] "Johnson Components recommended land pattern"
  round 95 hole 62: 1(0,0)
  round 100 hole 67: 2(100,100) 3(100,-100) 4(-100,-100) 5(-100,100)
  silkscreen extent -160,-160 160,160, body extent -156,-156 156,156, height 375
Johnson_142-0701-20x [mil] "Johnson Components recommended land pattern"
  round 95 hole 62: 1(0,0)
  round 100 hole 67: 2(100,100) 3(100,-100) 4(-100,-100) 5(-100,100)
  silkscreen extent -160,-160 160,160, body extent -156,-156 156,156, height 375
JOHNSON_142-0771-831 [mil] "JACK, SMA, 50 Ohm, Gold, Edge Mount"
  rect 22x218 smd: 1(0,-109)
  rect 138.25x218 smd: 2(-92.12,-109) 3(92.13,-109)
  rect 270x97.5 smd far side: 4(0,-48.75)
  round 16 hole 16: ""(-42,-25) ""(-42,-125) ""(-42,-75) ""(-42,-175) ""(42,-25) ""(42,-125) ""(42,-75) ""(42,-175)
  body extent -124,-179 123,375, height 131
Keystone5000 [mil] "For Keystone 500x miniature loop terminals"
  round 80 hole 40: 1(0,0)
  silkscreen extent -58,-58 58,58, body extent -49,-49 49,49, height 182
Keystone5007 [mil] "Keystone Compact loops"
  round 87 hole 63: 1(0,0)
  silkscreen extent -70,-70 70,70, body extent -63,-63 62,63, height 225
Keystone5010 [mil] "Keystone Multipurpose loops"
  round 87 hole 63: 1(0,0)
  silkscreen extent -70,-70 70,70, body extent -63,-63 63,62, height 319
Keystone5011 [mil] "Keystone Multipurpose loops"
  round 87 hole 63: 1(0,0)
  silkscreen extent -70,-70 70,70, body extent -63,-63 63,62, height 319
Keystone5012 [mil] "Keystone Multipurpose loops"
  round 87 hole 63: 1(0,0)
  silkscreen extent -70,-70 70,70, body extent -63,-63 63,62, height 319
Label_650x200 [mil] "Thermal Transfer Label"
  round 1 on Mech13: 0(0,0)
  silkscreen extent -325,-100 325,100, body extent -325,-100 325,100, height 1
LED_LTST-C190 [mm] "Lite-On"
  rect 0.8x0.8 smd: 1(-0.75,0) 2(0.75,0)
  silkscreen extent -1.1,-0.8 1.8,0.8, body extent -0.85,-0.45 0.85,0.45, height 0.9
LQFP-48_N [mm] "QFP, 48-Leads, Body 7x7mm, Pitch 0.5mm, IPC Medium Density"
  oval 1.65x0.3 smd: 1(-4.1,2.75) 2(-4.1,2.25) 3(-4.1,1.75) 4(-4.1,1.25) 5(-4.1,0.75) 6(-4.1,0.25) 7(-4.1,-0.25) 8(-4.1,-0.75) 9(-4.1,-1.25) 10(-4.1,-1.75) 11(-4.1,-2.25) 12(-4.1,-2.75) 25(4.1,-2.75) 26(4.1,-2.25) 27(4.1,-1.75) 28(4.1,-1.25) 29(4.1,-0.75) 30(4.1,-0.25) 31(4.1,0.25) 32(4.1,0.75) 33(4.1,1.25) 34(4.1,1.75) 35(4.1,2.25) 36(4.1,2.75)
  oval 0.3x1.65 smd: 13(-2.75,-4.1) 14(-2.25,-4.1) 15(-1.75,-4.1) 16(-1.25,-4.1) 17(-0.75,-4.1) 18(-0.25,-4.1) 19(0.25,-4.1) 20(0.75,-4.1) 21(1.25,-4.1) 22(1.75,-4.1) 23(2.25,-4.1) 24(2.75,-4.1) 37(2.75,4.1) 38(2.25,4.1) 39(1.75,4.1) 40(1.25,4.1) 41(0.75,4.1) 42(0.25,4.1) 43(-0.25,4.1) 44(-0.75,4.1) 45(-1.25,4.1) 46(-1.75,4.1) 47(-2.25,4.1) 48(-2.75,4.1)
  silkscreen extent -4.22,-2.88 2.88,3.57, body extent -3.5,-3.5 3.5,3.5, height 1.61
LTST-C191_Green [mm] "Lite-On"
  rect 0.8x0.8 smd: 1(-0.75,0) 2(0.75,0)
  silkscreen extent -1.1,-0.8 1.8,0.8, body extent -0.85,-0.45 0.85,0.45, height 0.65
M08A_N [mm] "SOIC, 8-Leads, Body 4.9x3.9mm, Pitch 1.27mm, IPC Medium Density"
  oval 2.2x0.6 smd: 1(-2.4,1.905) 2(-2.4,0.635) 3(-2.4,-0.635) 4(-2.4,-1.905) 5(2.4,-1.905) 6(2.4,-0.635) 7(2.4,0.635) 8(2.4,1.905)
  silkscreen extent -2.53,-2.5 0.9,2.88, body extent -2,-2.5 2,2.5, height 1.75
Mill-Max_800-10-004-10-001000 [mm] "Mill-Max"
  rect 1.5x1.5 hole 0.85: 1(-3.81,0)
  round 1.5 hole 0.85: 2(-1.27,0) 3(1.27,0) 4(3.81,0)
  silkscreen extent -5.75,-1.27 5.08,1.27, body extent -5.08,-1.27 5.08,1.27, height 8.13
Molex_0022284033 [mm] "Header, 2.54mm, 3x1, TH"
  rect 1.55x1.55 hole 1.02: 1(-2.54,0)
  round 1.55 hole 1.02: 2(0,0) 3(2.54,0)
  silkscreen extent -3.81,-1.24 3.81,1.5, body extent -3.81,-1.24 3.81,1.24, height 8.4
Molex_0853050232 [mm] "Plug, 50 Ohm, Straight, SMT"
  rrect17% 0.6x1.3 smd: 1(0,3.05)
  rrect25% 0.4x0.4 smd: 2(0,-2.3)
  Top Layer region: -2.6,-2.6 -2.6,2.6 -1,2.6 -1,1.732 -1.732,1 -2,0 -1.732,-1 -1,-1.732 0,-2 1,-1.732 1.732,-1 2,0 1.732,1 1,1.732 1,1.732 1,2.6 2.6,2.6 2.6,-2.6
  body extent -2.5,-2.5 2.5,3.5, height 4.1
Murata_NFM31P [mm] "SMD, 3-Leads, Body 3.2x1.6mm"
  rect 0.95x1 smd paste-2 mask-2: 1(-1.725,0) 3(1.725,0)
  rect 1x0.7 smd paste-2 mask+0: 2(0,0.65) 2(0,-0.65)
  silkscreen extent -2.59,-1.2 2.59,1.2, body extent -1.7,-0.9 1.7,0.9, height 1.5
NKD0064A [mm] "QFN, 64-Leads, Body 9x9mm, Pitch 0.5mm"
  rrect40% 0.6x0.25 smd: 1(-4.4,3.75) 2(-4.4,3.25) 3(-4.4,2.75) 4(-4.4,2.25) 5(-4.4,1.75) 6(-4.4,1.25) 7(-4.4,0.75) 8(-4.4,0.25) 9(-4.4,-0.25) 10(-4.4,-0.75) 11(-4.4,-1.25) 12(-4.4,-1.75) 13(-4.4,-2.25) 14(-4.4,-2.75) 15(-4.4,-3.25) 16(-4.4,-3.75) 33(4.4,-3.75) 34(4.4,-3.25) 35(4.4,-2.75) 36(4.4,-2.25) 37(4.4,-1.75) 38(4.4,-1.25) 39(4.4,-0.75) 40(4.4,-0.25) 41(4.4,0.25) 42(4.4,0.75) 43(4.4,1.25) 44(4.4,1.75) 45(4.4,2.25) 46(4.4,2.75) 47(4.4,3.25) 48(4.4,3.75)
  rrect40% 0.25x0.6 smd: 17(-3.75,-4.4) 18(-3.25,-4.4) 19(-2.75,-4.4) 20(-2.25,-4.4) 21(-1.75,-4.4) 22(-1.25,-4.4) 23(-0.75,-4.4) 24(-0.25,-4.4) 25(0.25,-4.4) 26(0.75,-4.4) 27(1.25,-4.4) 28(1.75,-4.4) 29(2.25,-4.4) 30(2.75,-4.4) 31(3.25,-4.4) 32(3.75,-4.4) 49(3.75,4.4) 50(3.25,4.4) 51(2.75,4.4) 52(2.25,4.4) 53(1.75,4.4) 54(1.25,4.4) 55(0.75,4.4) 56(0.25,4.4) 57(-0.25,4.4) 58(-0.75,4.4) 59(-1.25,4.4) 60(-1.75,4.4) 61(-2.25,4.4) 62(-2.75,4.4) 63(-3.25,4.4) 64(-3.75,4.4)
  rrect1% 7.2x7.2 smd paste-3.6: 65(0,0)
  silkscreen extent -4.65,-4.65 4.65,4.65, body extent -4.55,-4.55 4.55,4.55, height 0.81
OSC_CVHD-950-4 [mil] "Crystek recommended land pattern 2011-02-22 Rev H"
  rect 90x50 smd: 1(-140,100) 2(-140,-100) 3(140,-100) 4(140,100)
  silkscreen extent -200,-300 200,300, body extent -180,-280 180,280, height 209
Pb-Free_Overlay_Small [mil]
  silkscreen extent -46,-46 46,46
PGB1_0603 [mm] "Littelfuse"
  rect 1.27x0.76 smd: 1(-0.89,0) 2(0.89,0)
  silkscreen extent -1.8,-0.65 1.78,0.65, body extent -0.86,-0.44 0.86,0.44, height 0.36
PW0016A_N [mm] "TSOP, 16-Leads, Body 5x4.4mm, Pitch 0.65mm, IPC Medium Density"
  oval 1.4x0.45 smd: 1(-2.95,2.275) 2(-2.95,1.625) 3(-2.95,0.975) 4(-2.95,0.325) 5(-2.95,-0.325) 6(-2.95,-0.975) 7(-2.95,-1.625) 8(-2.95,-2.275) 9(2.95,-2.275) 10(2.95,-1.625) 11(2.95,-0.975) 12(2.95,-0.325) 13(2.95,0.325) 14(2.95,0.975) 15(2.95,1.625) 16(2.95,2.275)
  silkscreen extent -3.5,-2.55 1.85,2.75, body extent -3.21,-2.5 3.21,2.5, height 1
QFN16-3x3MM_0_5 [mm] "QFN, 16-Leads, Body 3x3mm, Pitch 0.5mm"
  rrect100% 0.6x0.3 smd: 1(-1.4,0.75) 2(-1.4,0.25) 3(-1.4,-0.25) 4(-1.4,-0.75) 9(1.4,-0.75) 10(1.4,-0.25) 11(1.4,0.25) 12(1.4,0.75)
  rrect100% 0.3x0.6 smd: 5(-0.75,-1.4) 6(-0.25,-1.4) 7(0.25,-1.4) 8(0.75,-1.4) 13(0.75,1.4) 14(0.25,1.4) 15(-0.25,1.4) 16(-0.75,1.4)
  rrect6% 1.7x1.7 smd paste-2: 17(0,0)
  silkscreen extent -1.6,-1.6 1.6,1.6, body extent -1.5,-1.5 1.5,1.5, height 1.01
RGR0020A [mm] "QFN, 20-Leads, Body 3.5x3.5mm, Pitch 0.5mm, Thermal Pad 2.05x2.05mm, TI Recommended"
  oval 0.6x0.24 smd: 1(-1.65,1) 2(-1.65,0.5) 3(-1.65,0) 4(-1.65,-0.5) 5(-1.65,-1) 11(1.65,-1) 12(1.65,-0.5) 13(1.65,0) 14(1.65,0.5) 15(1.65,1)
  oval 0.24x0.6 smd: 6(-1,-1.65) 7(-0.5,-1.65) 8(0,-1.65) 9(0.5,-1.65) 10(1,-1.65) 16(1,1.65) 17(0.5,1.65) 18(0,1.65) 19(-0.5,1.65) 20(-1,1.65)
  rect 2.05x2.05 smd paste-1.025: 21(0,0)
  silkscreen extent -1.97,-1.98 1.97,1.97, body extent -1.83,-1.83 1.83,1.83, height 1.01
RGW0020A [mm] "QFN, 20-Leads, Body 5x5mm, Pitch 0.65mm, Thermal Pad 3.15x3.15mm, TI Recommended"
  oval 0.75x0.3 smd: 1(-2.325,1.3) 2(-2.325,0.65) 3(-2.325,0) 4(-2.325,-0.65) 5(-2.325,-1.3) 11(2.325,-1.3) 12(2.325,-0.65) 13(2.325,0) 14(2.325,0.65) 15(2.325,1.3)
  oval 0.3x0.75 smd: 6(-1.3,-2.325) 7(-0.65,-2.325) 8(0,-2.325) 9(0.65,-2.325) 10(1.3,-2.325) 16(1.3,2.325) 17(0.65,2.325) 18(0,2.325) 19(-0.65,2.325) 20(-1.3,2.325)
  rect 3.15x3.15 smd paste-1.575: 21(0,0)
  silkscreen extent -2.73,-2.73 2.73,2.73, body extent -2.58,-2.57 2.57,2.58, height 1.01
RHA0040A [mm] "QFN, 40-Leads, Body 6x6mm, Pitch 0.5mm, Thermal Pad 4.6x4.6mm, TI Recommended"
  rrect40% 0.6x0.25 smd: 1(-2.9,2.25) 2(-2.9,1.75) 3(-2.9,1.25) 4(-2.9,0.75) 5(-2.9,0.25) 6(-2.9,-0.25) 7(-2.9,-0.75) 8(-2.9,-1.25) 9(-2.9,-1.75) 10(-2.9,-2.25) 21(2.9,-2.25) 22(2.9,-1.75) 23(2.9,-1.25) 24(2.9,-0.75) 25(2.9,-0.25) 26(2.9,0.25) 27(2.9,0.75) 28(2.9,1.25) 29(2.9,1.75) 30(2.9,2.25)
  rrect40% 0.25x0.6 smd: 11(-2.25,-2.9) 12(-1.75,-2.9) 13(-1.25,-2.9) 14(-0.75,-2.9) 15(-0.25,-2.9) 16(0.25,-2.9) 17(0.75,-2.9) 18(1.25,-2.9) 19(1.75,-2.9) 20(2.25,-2.9) 31(2.25,2.9) 32(1.75,2.9) 33(1.25,2.9) 34(0.75,2.9) 35(0.25,2.9) 36(-0.25,2.9) 37(-0.75,2.9) 38(-1.25,2.9) 39(-1.75,2.9) 40(-2.25,2.9)
  rrect2% 4.6x4.6 smd paste-2.3: 41(0,0)
  silkscreen extent -3.2,-3.17 3.18,3.18, body extent -3,-3 3,3, height 1
Rosenberger_32K101-400L5 [mm] "SMA, 50 Ohm, TH"
  rrect50% 2.2x2.2 hole 1.6: 1(0,0)
  round 2.2 hole 1.6: 2(-2.54,2.54) 3(2.54,2.54) 4(2.54,-2.54) 5(-2.54,-2.54)
  silkscreen extent -3.18,-3.18 3.18,3.18, body extent -3.17,-3.17 3.18,3.18, height 9.51
RTE-16 [mil]
  rect 32.24x11.8 smd mask+1: 1(-59.45,29.55) 2(-59.45,9.85) 3(-59.45,-9.85) 4(-59.45,-29.55) 9(59.55,-29.55) 10(59.55,-9.85) 11(59.55,9.85) 12(59.55,29.55)
  rect 11.8x32.24 smd mask+1: 5(-29.5,-59.5) 6(-9.8,-59.5) 7(9.9,-59.5) 8(29.6,-59.5) 13(29.6,59.5) 14(9.9,59.5) 15(-9.8,59.5) 16(-29.5,59.5)
  rect 57.09x57.09 smd mask+1.18: 17(0.15,-0.05)
  silkscreen extent -116,86 -86,116
RTV0032A [mm] "QFN, 32-Leads, Body 5x5mm, Pitch 0.5mm"
  rrect40% 0.6x0.25 smd: 1(-2.4,1.75) 2(-2.4,1.25) 3(-2.4,0.75) 4(-2.4,0.25) 5(-2.4,-0.25) 6(-2.4,-0.75) 7(-2.4,-1.25) 8(-2.4,-1.75) 17(2.4,-1.75) 18(2.4,-1.25) 19(2.4,-0.75) 20(2.4,-0.25) 21(2.4,0.25) 22(2.4,0.75) 23(2.4,1.25) 24(2.4,1.75)
  rrect40% 0.25x0.6 smd: 9(-1.75,-2.4) 10(-1.25,-2.4) 11(-0.75,-2.4) 12(-0.25,-2.4) 13(0.25,-2.4) 14(0.75,-2.4) 15(1.25,-2.4) 16(1.75,-2.4) 25(1.75,2.4) 26(1.25,2.4) 27(0.75,2.4) 28(0.25,2.4) 29(-0.25,2.4) 30(-0.75,2.4) 31(-1.25,2.4) 32(-1.75,2.4)
  rrect3% 3.1x3.1 smd paste-1.55: 33(0,0)
  silkscreen extent -2.7,-2.7 2.7,2.7, body extent -2.55,-2.55 2.55,2.55, height 0.81
Samtec_QSH-030-01-X-D-A#1 [mm] "Receptacle, 0.5 mm, 30x2, TH"
  rect 2.27x0.279 smd: 1(-2.865,7.25) 2(2.865,7.25) 3(-2.865,6.75) 4(2.865,6.75) 5(-2.865,6.25) 6(2.865,6.25) 7(-2.865,5.75) 8(2.865,5.75) 9(-2.865,5.25) 10(2.865,5.25) 11(-2.865,4.75) 12(2.865,4.75) 13(-2.865,4.25) 14(2.865,4.25) 15(-2.865,3.75) 16(2.865,3.75) 17(-2.865,3.25) 18(2.865,3.25) 19(-2.865,2.75) 20(2.865,2.75) 21(-2.865,2.25) 22(2.865,2.25) 23(-2.865,1.75) 24(2.865,1.75) 25(-2.865,1.25) 26(2.865,1.25) 27(-2.865,0.75) 28(2.865,0.75) 29(-2.865,0.25) 30(2.865,0.25) 31(-2.865,-0.25) 32(2.865,-0.25) 33(-2.865,-0.75) 34(2.865,-0.75) 35(-2.865,-1.25) 36(2.865,-1.25) 37(-2.865,-1.75) 38(2.865,-1.75) 39(-2.865,-2.25) 40(2.865,-2.25) 41(-2.865,-2.75) 42(2.865,-2.75) 43(-2.865,-3.25) 44(2.865,-3.25) 45(-2.865,-3.75) 46(2.865,-3.75) 47(-2.865,-4.25) 48(2.865,-4.25) 49(-2.865,-4.75) 50(2.865,-4.75) 51(-2.865,-5.25) 52(2.865,-5.25) 53(-2.865,-5.75) 54(2.865,-5.75) 55(-2.865,-6.25) 56(2.865,-6.25) 57(-2.865,-6.75) 58(2.865,-6.75) 59(-2.865,-7.25) 60(2.865,-7.25)
  round 1.02 hole 1.02 unplated mask+0.254: MH1(2.67,10.065) MH2(2.67,-10.065)
  rect 0.43x2.54 smd: MP1(0,8.065) MP4(0,-8.065)
  rect 0.43x4.7 smd: MP2(0,3.175) MP3(0,-3.175)
  silkscreen extent -3.9,-10.66 3.62,10.66, body extent -3.75,-10.64 3.75,10.67, height 3.25
Samtec_QSH-030-01-X-D-A#2 [mm] "Receptacle, 0.5 mm, 30x2, TH"
  rect 2.27x0.279 smd: 1(-2.865,7.25) 2(2.865,7.25) 3(-2.865,6.75) 4(2.865,6.75) 5(-2.865,6.25) 6(2.865,6.25) 7(-2.865,5.75) 8(2.865,5.75) 9(-2.865,5.25) 10(2.865,5.25) 11(-2.865,4.75) 12(2.865,4.75) 13(-2.865,4.25) 14(2.865,4.25) 15(-2.865,3.75) 16(2.865,3.75) 17(-2.865,3.25) 18(2.865,3.25) 19(-2.865,2.75) 20(2.865,2.75) 21(-2.865,2.25) 22(2.865,2.25) 23(-2.865,1.75) 24(2.865,1.75) 25(-2.865,1.25) 26(2.865,1.25) 27(-2.865,0.75) 28(2.865,0.75) 29(-2.865,0.25) 30(2.865,0.25) 31(-2.865,-0.25) 32(2.865,-0.25) 33(-2.865,-0.75) 34(2.865,-0.75) 35(-2.865,-1.25) 36(2.865,-1.25) 37(-2.865,-1.75) 38(2.865,-1.75) 39(-2.865,-2.25) 40(2.865,-2.25) 41(-2.865,-2.75) 42(2.865,-2.75) 43(-2.865,-3.25) 44(2.865,-3.25) 45(-2.865,-3.75) 46(2.865,-3.75) 47(-2.865,-4.25) 48(2.865,-4.25) 49(-2.865,-4.75) 50(2.865,-4.75) 51(-2.865,-5.25) 52(2.865,-5.25) 53(-2.865,-5.75) 54(2.865,-5.75) 55(-2.865,-6.25) 56(2.865,-6.25) 57(-2.865,-6.75) 58(2.865,-6.75) 59(-2.865,-7.25) 60(2.865,-7.25)
  round 1.02 hole 1.02 unplated mask+0.254: MH1(2.67,10.065)
  round 1.02 hole 1.02 unplated paste+0 mask+0.254: MH2(2.67,-10.065)
  rect 0.43x2.54 smd: MP1(0,8.065) MP4(0,-8.065)
  rect 0.43x4.7 smd: MP2(0,3.175) MP3(0,-3.175)
  silkscreen extent -3.9,-10.66 3.62,10.66, body extent -3.75,-10.64 3.75,10.67, height 3.25
SDA14B [mm] "SON, 14-Leads, Body 4x4mm, Pitch 0.5mm, NSC Recommended"
  rect 0.6x0.25 smd paste-0.125 mask+0.051: 1(-1.9,1.5) 2(-1.9,1) 3(-1.9,0.5) 4(-1.9,0) 5(-1.9,-0.5) 6(-1.9,-1) 7(-1.9,-1.5) 8(1.9,-1.5) 9(1.9,-1) 10(1.9,-0.5) 11(1.9,0) 12(1.9,0.5) 13(1.9,1) 14(1.9,1.5)
  rect 2.6x3 smd paste-1.3 mask+0.051: 15(0,0)
  silkscreen extent -3.02,-2.2 2.35,2.3, body extent -2.05,-2.05 2.05,2.05, height 0.8
SIA0008B [mm] "SIP 8-Leads, Body 5x7mm"
  rrect17% 1x0.6 on Bottom Paste: 1(-1.85,2.14) 1(-1.85,2.94) 2(-1.85,-0.4) 2(-1.85,0.4) 3(-1.85,-2.94) 3(-1.85,-2.14) 4(1.85,-2.94) 4(1.85,-2.14) 5(1.85,-0.4) 5(1.85,0.4) 6(1.85,2.14) 6(1.85,2.94)
  rrect10% 1x1.4 smd paste-0.5: 1(-1.85,2.54) 2(-1.85,0) 3(-1.85,-2.54) 4(1.85,-2.54) 5(1.85,0) 6(1.85,2.54)
  rrect12% 0.8x0.8 smd: 7(0,2.865) 8(0,-2.865)
  silkscreen extent -2.64,-3.63 2.64,3.63, body extent -2.56,-3.56 2.56,3.56, height 1.13
SMB-Bi [mil] "Molded Diode, 2-Leads, Body 5.4x3.6mm, IPC Medium Density, based on OnSemi component dimensions"
  rect 85x107.99 smd: 1(-87.01,0) 2(87.01,0)
  silkscreen extent -125,-79 125,79, body extent -104,-73 104,73, height 89
SOD-123 [mm] "On Semi recommended land pattern"
  rect 0.915x1.22 smd: 1(-1.637,0) 2(1.637,0)
  silkscreen extent -2.74,-1.17 2.03,1.17, body extent -1.93,-0.9 1.93,0.9, height 1.35
SOT-23 [mm] "SOT23, 3-Leads, Body 2.9x1.3mm, Pitch 0.95mm, Lead Span 2.5mm, IPC Medium Density"
  rrect50% 1x0.6 smd: 1(-1.2,0.95) 2(-1.2,-0.95) 3(1.2,0)
  silkscreen extent -1.62,-1.5 0.7,1.5, body extent -1.16,-1.45 1.21,1.45, height 1
SOT-23-6 [mm] "SOT23, 6-Leads, Body 3.0x1.7mm, Pitch 0.95mm, Lead Span 2.9mm, IPC Medium Density"
  rect 1.1x0.65 smd: 1(-1.2,0.95) 2(-1.2,0) 3(-1.2,-0.95) 4(1.2,-0.95) 5(1.2,0) 6(1.2,0.95)
  silkscreen extent -0.25,-1.55 0.25,1.55, body extent -1.5,-1.5 1.5,1.5, height 1.3
"SW_ L101011MS02Q" [mm] "SWITCH SLIDE sPST 4A PCB"
  rect 2.416x2.416 hole 1.65: 1(2.857,4.6)
  round 2.416 hole 1.65: 2(2.857,0) 3(2.858,-4.6)
  silkscreen extent -5.4,-9.55 5.4,9.55, body extent -5.39,-9.55 5.39,9.55, height 14.18
TCBS-6-01 [mil] "Richco Plastics"
  round 157 hole 157 unplated mask+10: 1(0,0)
  body extent -180,-156 180,156, height 375
TFMR_5_150X150_50 [mil] "TFMR_5_150X150_50"
  rect 65x30 smd: 1(-62.5,-50) 2(-62.5,0) 3(-62.5,50) 4(62.5,50) 6(62.5,-50)
  silkscreen extent -110,-90 110,90
TSW-102-07-G-S [mm] "Samtec 100mil, 1x2, 230 mil above insulator"
  rrect6% 1.65x1.65 hole 1.016: 1(-1.27,0)
  round 1.65 hole 1.016: 2(1.27,0)
  silkscreen extent -2.54,-1.27 2.54,1.65, body extent -2.54,-1.27 2.54,1.27, height 8.38
TSW-104-07-G-D [mm] "Samtec 100mil, 2x4, 230 mil above insulator"
  rrect6% 1.65x1.65 hole 1.016: 1(-3.81,-1.27)
  round 1.65 hole 1.016: 2(-3.81,1.27) 3(-1.27,-1.27) 4(-1.27,1.27) 5(1.27,-1.27) 6(1.27,1.27) 7(3.81,-1.27) 8(3.81,1.27)
  silkscreen extent -6.1,-2.54 5.08,2.54, body extent -5.08,-2.54 5.08,2.54, height 8.38
VSSOP8 [mil]
  rect 30x11 smd: 1(-63,29.5) 2(-63,9.8) 3(-63,-9.9) 4(-63,-29.6) 5(63,-29.6) 6(63,-9.9) 7(63,9.8) 8(63,29.5)
WEEE_Minimum [mil] "WEEElie bin"
  silkscreen extent -95,-172 99,104
XAL7030 [mm] "Coilcraft XAL7030 7.5 x.7.5 x 3.1 mm"
  rect 1.78x6.55 smd: 1(-2.36,0) 2(2.36,0)
  silkscreen extent -4,-4 4,4, body extent -4,-4 4,4, height 3.1
XTAL_ABM3 [mm] "Abracon recommended land pattern 12.28.10"
  rect 1.9x2.4 smd: 1(-2.05,0) 2(2.05,0)
  silkscreen extent -2.67,-1.78 2.67,1.78, body extent -2.6,-1.7 2.6,1.7, height 1.3

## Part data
C1 C14 C23 C108 C109 C110 C111 C113 C114 C115 C117 C120 C124 C198 C199: "CAP, CERM, 0.1uF, 25V, +/-5%, X7R, 0603", Cap_Case=0603, Manufacturer=Kemet, Supplier Part Number 1=399-1282-1-ND, TempCo=X7R, Tolerance_%=5, Value1=Unknown, Value2=25V, ValueDisplayed=0.1µF
C2 C35 C38 C40 C41 C135 C139 C144 C148 C153 C155 C160 C162 C164 C165 C175 C181: "CAP, CERM, 0.1 µF, 16 V, +/- 10%, X7R, 0402", Cap_Case=0402, Manufacturer=MuRata, Supplier Part Number 1=490-3261-1-ND, TempCo=X7R, Tolerance_%=10, Value1=Unknown, Value2=16V, ValueDisplayed=0.1µF
C3 C4 C5 C6 C9 C10 C12 C15 C16 C22 C173 C174 C178 C179 C184 C185 C186 C189 C190 C191 C202: "CAP, CERM, 0.1 µF, 25 V, +/- 20%, X7R, 0402", Cap_Case=0402, Manufacturer=TDK, Supplier Part Number 1=445-7349-1-ND, TempCo=X7R, Tolerance_%=20, Value1=Unknown, Value2=25V, ValueDisplayed=0.1µF
C7: "CAP, CERM, 47 pF, 25 V, +/- 5%, C0G/NP0, 0201", Cap_Case=0201, Manufacturer=MuRata, Supplier Part Number 1=490-1256-1-ND, TempCo=C0G/NP0, Tolerance_%=5, Value1=Unknown, Value2=25V, ValueDisplayed=47pF
C8: "CAP, CERM, 3900 pF, 10 V, +/- 10%, X5R, 0201", Cap_Case=0201, Manufacturer=AVX, Supplier Part Number 1=478-1046-1-ND, TempCo=X5R, Tolerance_%=10, Value1=Unknown, Value2=10V, ValueDisplayed=3900pF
